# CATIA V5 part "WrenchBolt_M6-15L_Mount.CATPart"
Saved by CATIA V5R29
Part number: WrenchBolt_M6-15L_Mount
Source: Unknown
Bounding box of the stored display mesh (mm): x -5.11 to 5.11, y -5.11 to 5.11, z -15 to 6
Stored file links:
  C:\가치같이\SmartFactory_BoxErectorConveyor\Boxing(under)\WrenchBolt_M6-15L_Mount.CATPart
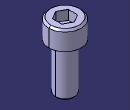
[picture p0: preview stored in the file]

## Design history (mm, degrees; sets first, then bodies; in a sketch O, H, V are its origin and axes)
Body1 (main body)
  Solid1 "PartBody": solid without history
